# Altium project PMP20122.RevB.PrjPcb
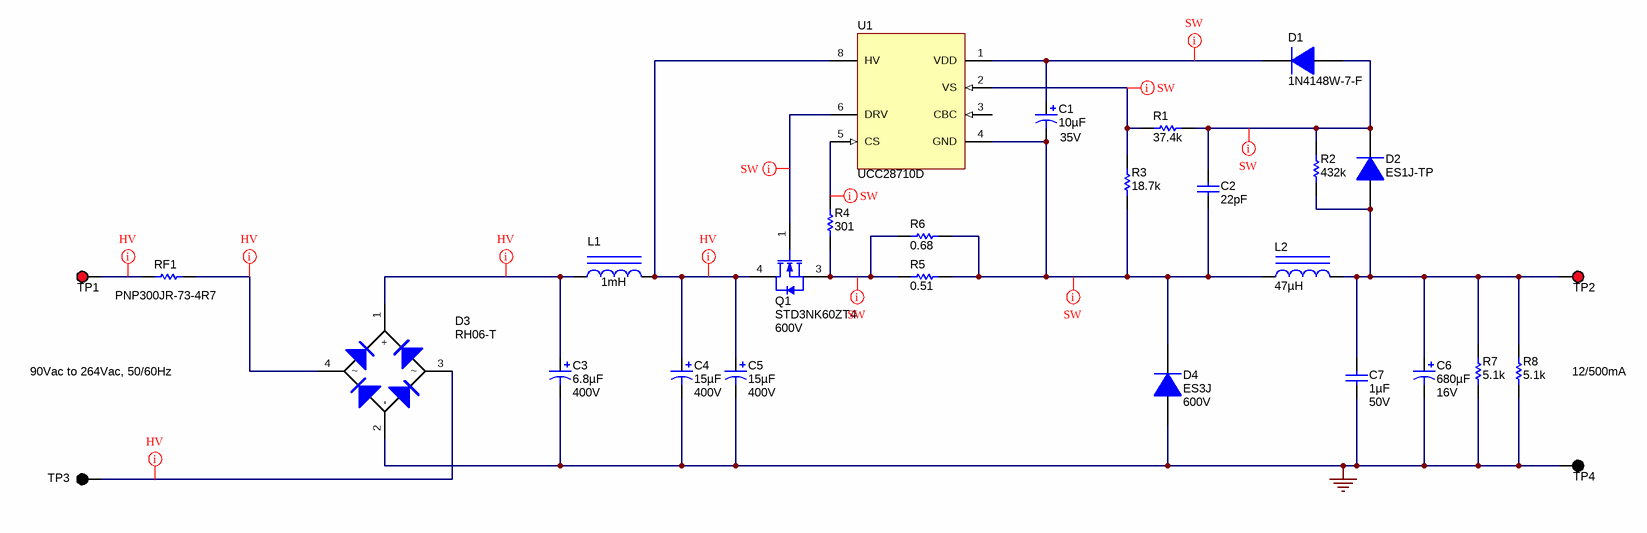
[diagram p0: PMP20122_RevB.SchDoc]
CopyrightYear: 2016; PCB_Layout: J Sanchez-Perez; PCB_Rev: B; PRJ_Customer: Public Release; PRJ_Engineer: N/A; PRJ_Number: PMP20122; PRJ_Title: UCC28710 High-side Buck Converter; SCH_Rev: B; TechSupport: http://www.ti.com/support
1 sheet, 28 parts. Net scope: global (net labels, ports and power ports of the same name join across sheets).
Board file: PMP20122.RevB_PCB.PcbDoc

## Sheet PMP20122_RevB.SchDoc: 90Vac- 265Vac to 12V/0.5A
size 431 x 279 mm; Date: Not shown in title block; ApprovedBy: Not shown in title block; CheckedBy: Not shown in title block; Author: Not shown in title block; CompanyName: Not shown in title block; DrawnBy: J Sanchez-Perez; Engineer: Not shown in title block; Organization: Not shown in title block; Address1: Not shown in title block; Address2: Not shown in title block; Address3: Not shown in title block; Address4: Not shown in title block; DocumentNumber: 1; SheetNumber: 1; SheetTotal: 1; PageSetup: Record=PageOptions¦CenterHorizontal=True¦CenterVertical=True¦PrintScale=1.00¦XCorrection=1.00¦YCorrection=1.00¦PrintKind=0¦BorderSize=5000000¦LeftOffset=0¦BottomOffset=0¦Orientation=2¦PaperLength=1000¦PaperWidth=1000¦Scale=100¦PaperSource=15¦PrintQuality=600¦MediaType=1¦DitherType=10¦PaperKind=Letter¦PrintScaleMode=1

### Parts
C1  ValueDisplayed: 10µF  Value2: 35V  [CAPPR2-5x11]  (hidden comment: UVR1V100MDD1TA)
C2  ValueDisplayed: 22pF  [0603]  (hidden comment: 06035A220JAT2A)
C3  ValueDisplayed: 6.8µF  Value2: 400V  [CAPPRD350W60D800H1100]  (hidden comment: 400AX6R8M8x11)
C4  ValueDisplayed: 15µF  Value2: 400V  [ED_1250x2000]  (hidden comment: EEU-ED2G150)
C5  ValueDisplayed: 15µF  Value2: 400V  [ED_1250x2000]  (hidden comment: EEU-ED2G150)
C6  ValueDisplayed: 680µF  Value2: 16V  [ZL_1000x1600]  (hidden comment: 16ZL680MEFC10X16)
C7  ValueDisplayed: 1µF  Value2: 50V  [0805_HV]  (hidden comment: 08055C105KAT2A)
D1  1N4148W-7-F  [SOD-123]
D2  ES1J-TP  [SMA]
D3  RH06-T  [MiniDIP]
D4  ES3J  value 600V  [SMC]
L1  ValueDisplayed: 1mH  [IND_WE-TI_XS]  (hidden comment: PartNumber)
L2  ValueDisplayed: 47µH  [SLF12575]  (hidden comment: SLF12575T-470M2R7-PF)
Q1  STD3NK60ZT4  value 600V  [DPAK]
R1  ValueDisplayed: 37.4k  [0603]  (hidden comment: CRCW060337K4FKEA)
R2  value 432k  [1206]  (hidden comment: CRCW1206432KFKEA)
R3  value 18.7k  [0603]  (hidden comment: CRCW060318K7FKEA)
R4  value 301  [0603]  (hidden comment: CRCW0603301RFKEA)
R5  ValueDisplayed: 0.51  [0805_HV]  (hidden comment: CRM0805-FX-R510ELF)
R6  ValueDisplayed: 0.68  [0805_HV]  (hidden comment: ERJ-6RQFR68V)
R7  value 5.1k  [1206]  (hidden comment: CRCW12065K10JNEA)
R8  value 5.1k  [1206]  (hidden comment: CRCW12065K10JNEA)
RF1  PNP300JR-73-4R7  [PNP300]
TP1  5000  [Keystone5000]  (value not drawn)
TP2  5000  [Keystone5000]  (value not drawn)
TP3  5001  [Keystone5001]  (value not drawn)
TP4  5001  [Keystone5001]  (value not drawn)
U1  UCC28710D  [D0007A_N]

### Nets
GND: C3.2(-) C4.2(-) C5.2(-) C6.2(-) C7.2 D3.2(-) D4.2(A) R7.1 R8.1 TP4.1
NetC1_1: C1.1(+) D1.1(K) U1.1(VDD)
NetC1_2: C1.2(-) C2.2 D4.1(K) L2.1 R3.1 R5.2 R6.2 U1.4(GND)
NetC2_1: C2.1 D1.2(A) D2.1(K) R1.1 R2.2
NetC3_1: C3.1(+) D3.1(+) L1.1
NetC4_1: C4.1(+) C5.1(+) L1.2 Q1.4(D) U1.8(HV)
NetC6_1: C6.1(+) C7.1 D2.2(A) L2.2 R2.1 R7.2 R8.2 TP2.1
NetD3_3: D3.3 TP3.1
NetD3_4: D3.4 RF1.2
NetQ1_1: Q1.1(G) U1.6(DRV)
NetQ1_3: Q1.3(S) R4.1 R5.1 R6.1
NetR1_2: R1.2 R3.2 U1.2(VS)
NetR4_2: R4.2 U1.5(CS)
NetRF1_1: RF1.1 TP1.1

Not connected (* = marked no-connect by the designer): U1 3(CBC)

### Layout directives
net class HV: NetC3_1, NetC4_1, NetD3_3, NetD3_4, NetRF1_1
net class SW: NetC1_1, NetC1_2, NetC2_1, NetQ1_1, NetQ1_3, NetR1_2, NetR4_2

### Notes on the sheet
- 90Vac to 264Vac, 50/60Hz
- 12/500mA

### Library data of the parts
C1 = UVR1V100MDD1TA: CAP, AL, 10uF, 35V, +/-20%, TH; Manufacturer: Nichicon; Polarized: Y; CompType: Capacitor; U/M: EA; Cap_F: 0.00001; Tolerance_%: 20; Value1: Unknown; VDC_V: 35; TaMin_C: -40; TaMax_C: 85; Cap_Case: 5x11
C2 = 06035A220JAT2A: CAP, CERM, 22pF, 50V, +/-5%, C0G/NP0, 0603; Manufacturer: AVX; Polarized: N; CompType: Capacitor; U/M: EA; Cap_F: 0.000000000022; Tolerance_%: 5; ESR_Ohm: 0.259; Value1: 0.259 ohm; VDC_V: 50; TaMin_C: -55; TaMax_C: 125
C3 = 400AX6R8M8x11: CAP, AL, 6.8uF, 400V, +/-20%, TH; Manufacturer: Rubycon; Polarized: Y; CompType: Capacitor; U/M: EA; Cap_F: 0.0000068; Tolerance_%: 20; Value1: Unknown; VDC_V: 400; TaMin_C: -40; TaMax_C: 105; Cap_Case: 8x11
C4 C5 = EEU-ED2G150: CAP, AL, 15 µF, 400 V, +/- 20%, TH; Manufacturer: Panasonic; Polarized: Y; CompType: Capacitor; Value: 15uF; U/M: EA; Cap_F: 0.000015; Tolerance_%: 20; Value1: Unknown; VDC_V: 400; IRMS_A: 0.41; TaMin_C: -25; TaMax_C: 105; Cap_Case: 12.5x20mm; AEC Category: Q200; AEC Qualified: N
C6 = 16ZL680MEFC10X16: CAP, AL, 680 µF, 16 V, +/- 20%, 0.038 ohm, TH; Manufacturer: Rubycon; Polarized: Y; CompType: Capacitor; Value: 680uF; U/M: EA; Cap_F: 0.00068; Tolerance_%: 20; VDC_V: 16; ESR_ohm: 0.038; IRMS_A: 1.43; TaMin_C: -40; TaMax_C: 105; Cap_Case: 10x16mm; AEC Category: Q200; AEC Qualified: N
C7 = 08055C105KAT2A: CAP, CERM, 1uF, 50V, +/-10%, X7R, 0805; Manufacturer: AVX; Polarized: N; CompType: Capacitor; U/M: EA; Cap_F: 0.000001; Tolerance_%: 10; Value1: Unknown; VDC_V: 50; TaMin_C: -55; TaMax_C: 125; Cap_Case: 0805
D1 = 1N4148W-7-F: Diode, Ultrafast, 100V, 0.15A, SOD-123; Manufacturer: Diodes Inc.; U/M: EA; Vf_V: 1.25; Value2: 1.25V; Io_A: 0.15; Vr_V: 100; TJmax_C: 150
D2 = ES1D-13-F: DIODE FAST REC 600V 1A DO214AC; Manufacturer: Diodes Inc.; U/M: EA; Io_A: 1; Vr_V: 600; TJmax_C: 150; RJC_CperW: 25; Type: Ultrafast
D3 = RH06-T: Diode, Switching-Bridge, 600V, 0.5A, MiniDIP; Manufacturer: Diodes Inc.; U/M: EA; Vf_V: 1.15; Value2: 1.15V; Io_A: 0.5; Vr_V: 600; TJmax_C: 150
D4 = ES3J: Diode, Fast Rectifier, 600 V, 3 A, SMC; Manufacturer: Fairchild Semiconductor; U/M: EA; Vf_V: 1.7; Value1: 3A; Value2: 1.7V; Io_A: 3; Vr_V: 600; TJmax_C: 150; SizeAreaWB_mm2: 83.2686; SizeArea_mm2: 50.5686; SizeX_mm: 8.13; SizeY_mm: 6.22; SizeZ_mm: 2.6; AEC Category: Q101; AEC Qualified: N
L1 = 7447462102: Inductor, Unshielded Drum Core, Ferrite, 1mH, 0.25A, 4.38 ohm, TH; Manufacturer: Wurth Elektronik eiSos; Ind_H: 1.0E-3; Imax_A: 0.25; Irms: 0.25A @ 40C rise; Isat: 0.27A @ 10% inductance drop; DCR_ohm: 4.38; U/M: EA
L2 = SLF12575T-470M2R7-PF: Inductor, Shielded, Ferrite, 47 µH, 3 A, 0.0528 ohm, SMD; Manufacturer: TDK; Value: 47uH; Ind_H: 47.0E-6; Imax_A: 3; Irms: 3A @ 40C rise; Isat: 2.7A @ 10% inductance drop; DCR_ohm: 0.0528; Value2: 3A; AEC Category: Q200
Q1 = STD13NM60N: MOSFET N-CH 600V 2.4A DPAK; Manufacturer: ST Microelectronics; Alternate Manufacturer: None; U/M: EA; ChType: N; VdsMax_V: 600; Value1: 0.36 ohm; Rdson45_Ohm: 0.36; Value2: 30 nC; QgTyp_nC: 30; Vgs_V: 4; IdsMax_A: 3
R1 = CRCW060337K4FKEA: RES, 37.4 k, 1%, 0.1 W, 0603; Manufacturer: Vishay-Dale; CompType: Resistor; Value: 37.4k; Res_ohm: 37400; Value_Code: 37k4; Tolerance_%: 1; Power_W: 0.1; Value2: 0.1W; VDC_V: 75; TempCo: 100 ppm/C; EIA_Code: E96; U/M: EA; AEC Category: Q200
R2 = CRCW1206432KFKEA: RES, 432k ohm, 1%, 0.25W, 1206; Manufacturer: Vishay-Dale; CompType: Resistor; Res_ohm: 432000; Tolerance_%: 1; Power_W: 0.25; VDC_V: 200; TempCo: 100 ppm/C; EIA_Code: E96; U/M: EA
R3 = CRCW060318K7FKEA: RES, 18.7k ohm, 1%, 0.1W, 0603; Manufacturer: Vishay-Dale; CompType: Resistor; Res_ohm: 18700; Value_Code: 18k7; Tolerance_%: 1; Power_W: 0.1; VDC_V: 75; TempCo: 100 ppm/C; EIA_Code: E96; U/M: EA
R4 = CRCW0603301RFKEA: RES, 301 ohm, 1%, 0.1W, 0603; Manufacturer: Vishay-Dale; CompType: Resistor; Value_Code: 301R; Tolerance_%: 1; Power_W: 0.1; VDC_V: 75; TempCo: 100 ppm/C; EIA_Code: E96; U/M: EA
R5 = CRM0805-FX-R510ELF: RES, 0.51, 1%, 0.25 W, 0805; Manufacturer: Bourns; CompType: Resistor; Value: 0.51; Value_Code: R510; Tolerance_%: 1; Power_W: 0.25; Value2: 0.25W; VDC_V: 0; TempCo: 100 ppm/C; EIA_Code: E96; U/M: EA; AEC Category: Q200
R6 = ERJ-6RQFR68V: RES, 0.68, 1%, 0.125 W, 0805; Manufacturer: Panasonic; CompType: Resistor; Value: 0.68; Value_Code: R680; Tolerance_%: 1; Power_W: 0.125; Value2: 0.125W; TempCo: 250 ppm/C; EIA_Code: E96; U/M: EA; AEC Category: Q200
R7 R8 = CRCW12065K10JNEA: RES, 5.1k ohm, 5%, 0.25W, 1206; Manufacturer: Vishay-Dale; CompType: Resistor; Res_ohm: 5100; Value_Code: 5k10; Tolerance_%: 5; Power_W: 0.25; VDC_V: 200; TempCo: 200 ppm/C; EIA_Code: E24; U/M: EA
RF1 = PNP300JR-73-4R7: RES, 4.7, 5%, 3 W, 3W Axial resistor; Manufacturer: Yageo America; Value: 4.7; Value_Code: 4R70; Tolerance_%: 5; Power_W: 3; TempCo: 300 ppm/C; EIA_Code: E24; U/M: EA; AEC Category: Q200; AEC Qualified: N
TP1 TP2 = 5000: Test Point, Miniature, Red, TH; Manufacturer: Keystone; CompType: Test Point Loop; U/M: EA
TP3 TP4 = 5001: Test Point, TH, Miniature, Black; Manufacturer: Keystone; Alternate Manufacturer: Any; Alternate PartNumber: Equivalent; CompType: Test Point Loop; U/M: EA
U1 = UCC28710D: Constant-Voltage, Constant-Current Controller With Primary-Side Regulation, D0007A; Alternate Manufacturer: None; Manufacturer: Texas Instruments; SymbolCreator: a0411947; CompType: IC; U/M: EA

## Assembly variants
001: not fitted FID1 FID2 FID3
